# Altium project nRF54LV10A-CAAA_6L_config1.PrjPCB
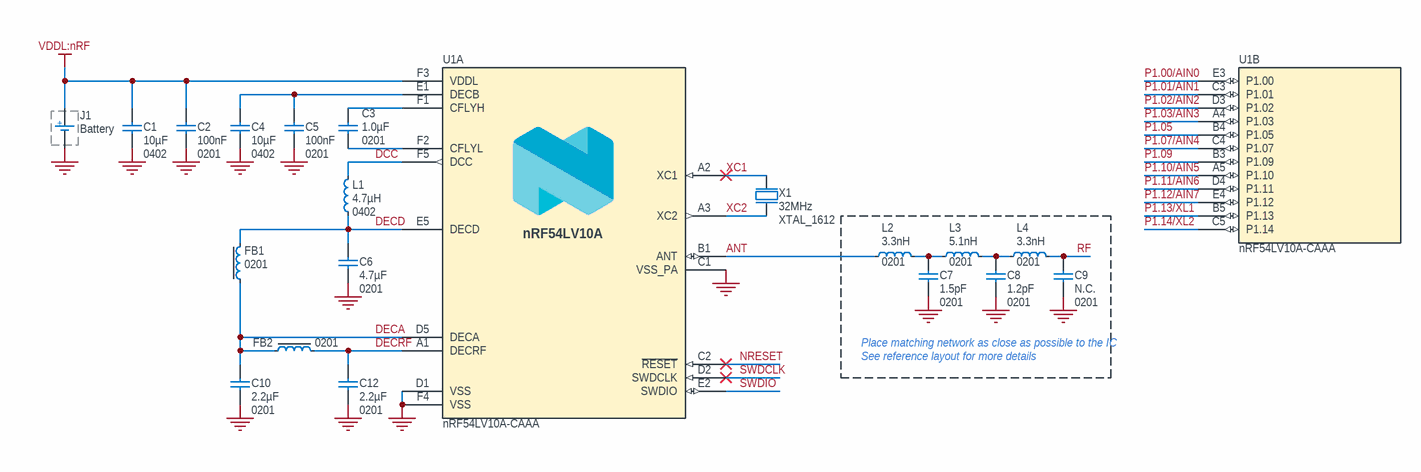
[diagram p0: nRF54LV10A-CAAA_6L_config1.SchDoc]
Revision: 0.7; RefLayoutTitle: 1.2V to 1.7V VDDL Supply,  Enabled DC/DC - 6 Layer PCB; DrawnBy: Nordic Semiconductor; Device: nRF54LV10A-CAAA; Config: 1; Classification: Public
1 sheet, 20 parts. Net scope: strictly hierarchical (ports join the sheet entries above them; power ports are local).
Board file: nRF54LV10A-CAAA_6L_config1.PcbDoc

## Sheet nRF54LV10A-CAAA_6L_config1.SchDoc
size A4; Organization: Nordic Semiconductor; SheetNumber: 1; SheetTotal: 1; DocumentSize: A4

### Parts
C1  10µF  Footprint Doc: 0402  [CAPC1005X04L]
C2  100nF  Footprint Doc: 0201  [CAPC0603X03L_C]
C3  1.0µF  Footprint Doc: 0201  [CAPC0603X03L_C]
C4  10µF  Footprint Doc: 0402  [CAPC1005X04L]
C5  100nF  Footprint Doc: 0201  [CAPC0603X03L_C]
C6  4.7µF  Footprint Doc: 0201  [CAPC0603X03L_C]
C7  1.5pF  Footprint Doc: 0201  [CAPC0603X03L_C]
C8  1.2pF  Footprint Doc: 0201  [CAPC0603X03L_C]
C9  N.C.  Footprint Doc: 0201  [CAPC0603X03L_C_NC]
C10  2.2µF  Footprint Doc: 0201  [CAPC0603X03L_C]
C12  2.2µF  Footprint Doc: 0201  [CAPC0603X03L_C]
FB1  Footprint Doc: 0201  [INDC0603X03L_C]  (hidden comment: 120R/0.2A)
FB2  Footprint Doc: 0201  [INDC0603X03L_C]  (hidden comment: 120R/0.2A)
J1  Battery  [TP_2x1mm_TH]  (graphical)
L1  4.7µH  Footprint Doc: 0402  [INDDFN10X06X08L31X32L]
L2  3.3nH  Footprint Doc: 0201  [INDC0603X03L_C]
L3  5.1nH  Footprint Doc: 0201  [INDC0603X03L_C]
L4  3.3nH  Footprint Doc: 0201  [INDC0603X03L_C]
U1  nRF54LV10A-CAAA  [BGA29CP35_5X6_239X201X45B20]  (parts A,B of 2)
X1  32MHz  Footprint Doc: XTAL_1612  [BT-XTAL_1612]

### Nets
GND: C1.1 C2.2 C4.1 C5.2 C6.1 C7.2 C8.2 C9.1 C10.1 C12.1 J1.1(GND) U1.C1(VSS_PA) U1.D1(VSS) U1.F4(VSS) X1.2(GND) X1.4(GND)
VDDL:nRF: C1.2 C2.1 J1.2(V+) U1.F3(VDDL)
ANT: L2.1 U1.B1(ANT)
DCC: L1.1 U1.F5(DCC)
DECA: C10.2 FB1.2 FB2.2 U1.D5(DECA)
DECD: C6.2 FB1.1 L1.2 U1.E5(DECD)
DECRF: C12.2 FB2.1 U1.A1(DECRF)
NRESET: U1.C2(~{RESET})
P1.00/AIN0: U1.E3(P1.00)
P1.01/AIN1: U1.C3(P1.01)
P1.02/AIN2: U1.D3(P1.02)
P1.03/AIN3: U1.A4(P1.03)
P1.05: U1.B4(P1.05)
P1.07/AIN4: U1.C4(P1.07)
P1.09: U1.B3(P1.09)
P1.10/AIN5: U1.A5(P1.10)
P1.11/AIN6: U1.D4(P1.11)
P1.12/AIN7: U1.E4(P1.12)
P1.13/XL1: U1.B5(P1.13)
P1.14/XL2: U1.C5(P1.14)
RF: C9.2 L4.2
SWDCLK: U1.D2(SWDCLK)
SWDIO: U1.E2(SWDIO)
XC1: U1.A2(XC1) X1.1(inp)
XC2: U1.A3(XC2) X1.3(out)
NetC3_1: C3.1 U1.F2(CFLYL)
NetC3_2: C3.2 U1.F1(CFLYH)
NetC4_2: C4.2 C5.1 U1.E1(DECB)
NetC7_1: C7.1 L2.2 L3.1
NetC8_1: C8.1 L3.2 L4.1

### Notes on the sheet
- See reference layout for more details
- Place matching network as close as possible to the IC

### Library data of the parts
C1 C4 = C0402-10µF-6.3V-X6S: Capacitor, X6S, ±20%, 6.3V; Manufacturer: N.A.; Component Status: Active; Pad Count: 2
C2 C5 = C0201-100n-10V-X7R: Capacitor, X7R, ±10%, 10V; Manufacturer: N.A.; Pad Count: 2; Component Status: Active
C3 = C0201-1µ0-6.3V: Capacitor, Ceramic, X5R, ±20%, 6.3V; Manufacturer: N.A.; Component Status: Active; Pad Count: 2
C6 = C0201-4.7µ-6V3-X5R-GRM035R60J475ME15J: Capacitor, Ceramic, X5R, ±20%, 6.3V; Manufacturer: N.A.; Component Status: Active; Pad Count: 2; Note: -55°C ~ 85°C
C7 = C0201-1.5p_RF: RF Chip Cap 0201; Manufacturer: N.A.; Component Status: Active; Pad Count: 2; Note: High frequency chip capasitors ±5%, NP0
C8 = C0201-1.2p-HQ-Murata: Capacitor, NP0, ±0.05pF, 50V; Manufacturer: N.A.; Component Status: Active; Pad Count: 2
C9 = C0201-N.C.: Not mounted; Manufacturer: N.A.; Component Status: Active; Pad Count: 2; Note: Chip Cap; Assembly: Not mounted
C10 C12 = C0201-2µ2-2.5V-X6T-GRM033D80E225ME47D: Capacitor, Ceramic, 2.2µF 2.5V X6T 0201,±20%; Manufacturer: N.A.; Component Status: Active; Pad Count: 2; Note: 2.5V, 20%, X6T
FB1 FB2 = FB0201-120R@100M-200mA-BLM03AG121SN1D: Ferrite Bead, 120 Ohm @ 100MHz, 200mA, 500 mOhm Max; Manufacturer: N.A.; Component Status: Active; Pad Count: 2
J1 = Battery_TP: Manufacturer: N.A.; Part number NEMS: 101800006; Component Status: Active; Pad Count: 3
L1 = L0402-4µ7-PLEA67BCA4R7M-1PT00: Inductor, 300mA, ±20%, 1.08R; Manufacturer: N.A.; Component Status: Active; Pad Count: 2; Note: Power Inductor ±20%
L2 L4 = L0201-3n3-HQ-Murata: Inductor, 500mA, ±0.1ｎH, 170mOhm; Manufacturer: Murata; Manufacturer Part Number: LQP03HQ3N3B02; Component Status: Active; Pad Count: 2; Note: -55°C ~ 125°C; Artikkelnr Noca: N.A.
L3 = L0201-5n1-HQ-Murata: Inductor, 400mA, ±3%, 250mOhm; Manufacturer: Murata; Manufacturer Part Number: LQP03HQ5N1H02; Component Status: Active; Pad Count: 2; Note: -55°C ~ 125°C; Artikkelnr Noca: N.A.
U1 = nRF54LV10A-CAAA: Multi-protocol Bluetooth Low Energy, IEEE 802.15.4 and 2.4GHz proprietary Wireless MCU; Manufacturer: Nordic Semiconductor; Component Status: Active; Pad Count: 29; Note: N.A.
X1 = XTAL_SMD1612_32MHz_8pF_Kyocera: XTAL SMD 1612, 32MHz, Cl=8pF, Tot: ±40ppm, Aging: ±1ppm/year; Manufacturer: N.A.; Component Status: Active; Pad Count: 4; Note: XTAL SMD 32.000MHz

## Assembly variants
Default: all parts fitted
